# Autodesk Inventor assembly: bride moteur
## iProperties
Author: chr
Created: 2002-03
Part Number: bride moteur
Document SubType Name: Assemblage
Designer: chr
Control State: 0
Master: False
Checked Out: False
PropertySet Name: Design Tracking Control
Shininess: 41.0
Angle Display Precision: 2
Document Length Units: 11269
Document Angle Units: 11283
Document Time Units: 11279
Document Mass Units: 11290
Document Length Units Precision: 3
Document Angle Units Precision: 2
Compacted: False
PropertySet Name: _Private Model Information
Density: 0.0
Volumn: 0.0
Area: 0.0
PropertySet Name: Model Information
